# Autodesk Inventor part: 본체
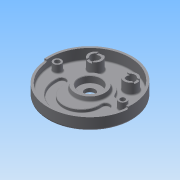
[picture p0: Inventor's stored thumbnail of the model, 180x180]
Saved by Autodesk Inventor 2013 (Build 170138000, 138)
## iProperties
Created: 2015-04
Part Number: 본체
Material: 일반
Document SubType Name: Modeling
Designer: Administrator
Density: 1 g/cm^3
Author: Administrator
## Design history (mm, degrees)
sketch "스케치1"
  geometry: C1 r 95 at (0, 0); 1 further point
  constraints: 1 centre point, 1 coincident
  dimensions: "d0" = 95 radius of C1
extrude "돌출1" new body sketch "스케치1" distance "d1" = 27; taper "d2" = 0 deg
feature "쉘1" dims "d3" = 7, "d4" = 5
sketch "스케치2"
  geometry: L1 (-94.638, -8.28)-(-89.658, -7.844); L2 (89.658, -7.844)-(94.638, -8.28); L3 (0, 0)-(85.276, 0); L4 (-89.658, -7.844)-(0, 0); L5 (0, 0)-(89.658, -7.844); C1 r 90 at (0, 0) reference; A1 r 90 centre (0, 0) between (-89.658, -7.844) and (89.658, -7.844) reference; A2 r 95 centre (0, 0) between (-94.638, -8.28) and (94.638, -8.28) reference
  constraints: 10 end point, 4 point on circle, 2 collinear, 1 horizontal
  dimensions: "d5" = 5 deg angle of L2 L3; "d6" = 5 deg angle of L3 L1
extrude "돌출2" join sketch "스케치2" distance "d7" = 5; taper "d8" = 0 deg
sketch "스케치3"
  geometry: L1 (-40.249, 12)-(-89.196, 12); L2 (40.249, 12)-(89.196, 12); A1 r 90 centre (0, 0) between (-89.196, 12) and (89.196, 12) reference; A2 r 42 centre (0, 0) between (40.249, 12) and (-40.249, 12)
  constraints: 4 end point, 4 point on circle, 1 centre point, 1 coincident, 1 collinear, 1 horizontal
  dimensions: "d9" = 42 radius of A2; "d10" = 12 distance from line of A1.centre L1; "d12" = 12 distance from line of A1.centre L2
extrude "돌출3" join sketch "스케치3" distance "d13" = 7; taper "d14" = 0 deg
sketch "스케치4"
  geometry: C1 r 35 at (0, 0); A1 r 42 centre (0, 0) between (40.249, 12) and (-40.249, 12) reference
  constraints: 1 centre point, 1 coincident
  dimensions: "d15" = 70 diameter of C1
extrude "돌출4" join sketch "스케치4" distance "d16" = 10; taper "d17" = -10 deg
hole "구멍1" diameter "d20" = 23; stored, may be unused: countersink angle "d24" = 90 deg, drill point angle "d26" = 118 deg; dims "d18" = 10, "d19" = 10, "d21" = 6, "d22" = 50, "d23" = 15, "d25" = 8
fillet "모깎기1" dims "d27" = 0.3
sketch "스케치5"
  geometry: C1 r 35 at (0, 0) reference; A1 r 9 centre (-49.749, -14) between (-40.794, -14.9) and (-58.704, -13.1); A2 r 9 centre (49.749, -14) between (58.704, -13.1) and (40.794, -14.9); A3 r 59 centre (0, -19) between (-58.704, -13.1) and (58.704, -13.1); A4 r 41 centre (0, -19) between (-40.794, -14.9) and (40.794, -14.9)
  constraints: 8 point on circle, 4 centre point, 2 tangent, 1 coincident, 1 horizontal alignment, 1 vertical alignment
  dimensions: "d29" = 19 distance of A3.centre C1.centre; "d31" = 18 diameter of A1; "d32" = 18 diameter of A2; "d33" = 5 vertical distance of A3.centre A1.centre; "d34" = 41 radius of A4; "d35" = 59 radius of A3
extrude "돌출5" cut sketch "스케치5" distance "d36" = 7; taper "d37" = 0 deg
fillet "모깎기2" dims "d38" = 1
chamfer "모따기1" distance "d39" = 1; stored, may be unused: second distance "d40" = 2, angle "d41" = 45 deg
sketch "스케치6"
  geometry: C1 r 9 at (-74, 0); C2 r 9 at (74, 0); A1 r 90 centre (0, 0) between (-89.196, 12) and (89.196, 12) reference
  constraints: 2 centre point, 2 horizontal alignment
  dimensions: "d42" = 18 diameter of C1; "d43" = 18 diameter of C2; "d44" = 148 distance of C2.centre C1.centre; "d45" = 74 distance of A1.centre C2.centre
extrude "돌출6" join sketch "스케치6" stored distance "d46" = 7; taper "d47" = 0 deg
sketch "스케치7"
  geometry: C1 r 9 at (-74, 0) reference; C2 r 9 at (74, 0) reference; 2 further points
  constraints: 2 coincident
hole "구멍2" sketch "스케치7" at (-74, 0), (74, 0) diameter "d48" = 11; stored, may be unused: countersink angle "d52" = 90 deg, drill point angle "d54" = 118 deg; dims "d49" = 6, "d50" = 18, "d51" = 11, "d53" = 8
sketch "스케치8"
  geometry: C1 r 15 at (-40, 52); C2 r 15 at (40, 52); A1 r 42 centre (0, 0) between (40.249, 12) and (-40.249, 12) reference
  constraints: 2 centre point, 1 horizontal alignment
  dimensions: "d55" = 30 diameter of C1; "d56" = 30 diameter of C2; "d57" = 80 distance of C2.centre C1.centre; "d58" = 40 horizontal distance of A1.centre C1.centre; "d59" = 52 vertical distance of C1.centre A1.centre
extrude "돌출7" join sketch "스케치8" stored distance "d60" = 7; taper "d61" = 0 deg
sketch "스케치9"
  geometry: C1 r 15 at (0, 0) reference; C2 r 15 at (-80, 0) reference; C3 r 10 at (-80, 0); C4 r 10 at (0, 0); 1 further point
  constraints: 2 centre point, 2 coincident
  dimensions: "d62" = 20 diameter of C3; "d63" = 20 diameter of C4
extrude "돌출8" cut sketch "스케치9" stored distance "d64" = 7; taper "d65" = 0 deg
sketch "스케치10"
  geometry: L1 (6, -15)-(-6, -15); L2 (-6, -15)-(-6, 15); L3 (-6, 15)-(6, 15); L4 (6, 15)-(6, -15); L5 (6, -15)-(-6, 15); L6 (-6, -15)-(6, 15); L7 (95, -6)-(65, -6); L8 (65, -6)-(65, 6); L9 (65, 6)-(95, 6); L10 (95, 6)-(95, -6); L11 (95, -6)-(65, 6); L12 (65, -6)-(95, 6); C1 r 10 at (80, 0) reference; 5 further points
  constraints: 24 end point, 6 midpoint, 4 parallel, 2 horizontal, 2 perpendicular, 1 horizontal alignment, 1 vertical alignment, 2 other
  dimensions: "d66" = 12 distance of L2.end L3.end; "d68" = 12 distance of L7.end L8.end
extrude "돌출9" cut sketch "스케치10" distance "d69" = 3; taper "d70" = 0 deg
fillet "모깎기3" dims "d71" = 10
fillet "모깎기4" dims "d72" = 3
chamfer "모따기2" distance "d73" = 1; stored, may be unused: second distance "d74" = 2, angle "d75" = 45 deg
fillet "모깎기5" dims "d76" = 3
sketch "스케치13"
  geometry: L1 (0, 0)-(36.062, -36.062); L2 (0, 0)-(51, 0); L3 (36.062, -36.062)-(50.912, -50.912); L4 (0, 0)-(-36.062, -36.062); L5 (-50.912, -50.912)-(-36.062, -36.062); C1 r 12.5 at (0, 0) reference; A1 r 51 centre (0, 0) between (-36.062, -36.062) and (36.062, -36.062); A2 r 72 centre (0, 0) between (-50.912, -50.912) and (50.912, -50.912)
  constraints: 10 end point, 4 point on circle, 2 centre point, 2 coincident, 2 collinear, 1 equal length, 1 horizontal, 1 perpendicular
  dimensions: "d80" = 51 distance of L1.end L1.start; "d81" = 45 deg angle of L1 L2; "d82" = 72 radius of A2
extrude "돌출10" join sketch "스케치13" distance "d83" = 5; taper "d84" = 0 deg
fillet "모깎기6" dims "d85" = 5
fillet "모깎기7" dims "d86" = 3
fillet "모깎기8" dims "d87" = 5
sketch "스케치14"
  geometry: C1 r 68 at (0, 0); 1 further point
  constraints: 1 centre point, 1 coincident, 1 other
  dimensions: "d88" = 136 diameter of C1
feature "엠보싱2" sketch "스케치14" dims "d1" = 27, "d2" = 0, "d91" = 0.5, "d92" = 0
fillet "모깎기9" dims "d93" = 5
node "솔리드1"
node "투영된 루프1"
node "투영된 루프2"
other parameters: "d28" = 118, "d30" = 82, "d78" = 144
